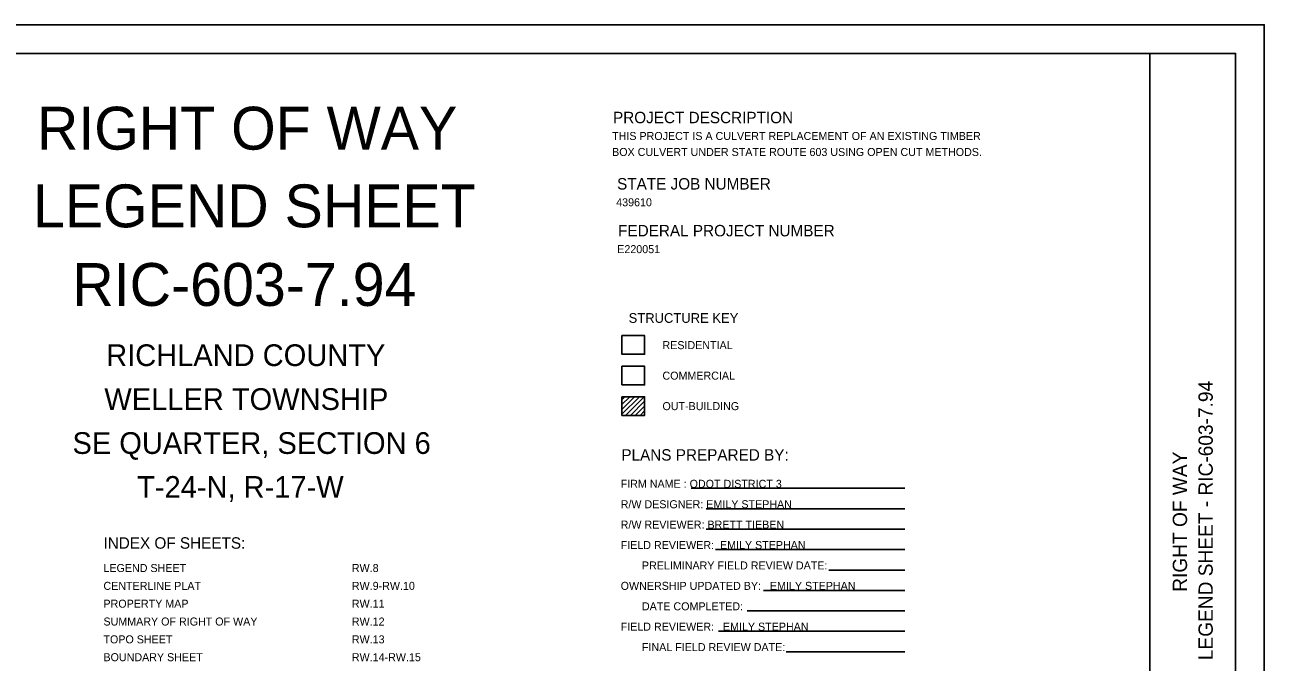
# Model space of a CAD drawing. Extents: x 0 to 34, y 0 to 22.
# Drawn here: x 12.32 to 34, y 10.85 to 22 of the extents above; entities that cross this region are included whole.
import ezdxf

# ---------------------------------------------------------------- set-up
doc = ezdxf.new("R2010")
doc.units = 0
for name, color, linetype in [('SC_Shading1', 7, 'Continuous'), ('SH_Border', 7, 'Continuous'), ('SH_Cut_Line', 7, 'Continuous'), ('SH_Data', 7, 'Continuous'), ('SH_Text', 7, 'Continuous')]:
    doc.layers.add(name, color=color, linetype=linetype)

msp = doc.modelspace()

# ---------------------------------------------------------------- linework, layer by layer
at = {"layer": 'SC_Shading1'}
msp.add_lwpolyline([(22.763, 15.701), (23.16, 15.701), (23.16, 16.027), (22.763, 16.027)], close=True, dxfattribs=at)
at = {"layer": 'SH_Border'}
msp.add_line((32, 0.5), (32, 21.5), dxfattribs=at)
msp.add_lwpolyline([(1.5, 21.5), (33.5, 21.5), (33.5, 0.5), (1.5, 0.5)], close=True, dxfattribs=at)
at = {"layer": 'SH_Cut_Line'}
msp.add_lwpolyline([(0, 0), (34, 0), (34, 22), (0, 22)], close=True, dxfattribs=at)
at = {"layer": 'SH_Text'}
for p, q in [((22.763, 15.491), (22.764, 15.492)), ((22.763, 15.441), (22.814, 15.492)), ((22.763, 15.356), (22.899, 15.492)), ((22.763, 15.271), (22.983, 15.492)), ((22.763, 15.186), (23.068, 15.492)), ((22.827, 15.166), (23.153, 15.492)), ((22.912, 15.166), (23.16, 15.414)), ((22.996, 15.166), (23.16, 15.329)), ((23.081, 15.166), (23.16, 15.245)), ((22.763, 15.171), (22.767, 15.166)), ((23.973, 13.891), (27.71, 13.891)), ((24.237, 13.533), (27.71, 13.533)), ((24.237, 13.176), (27.71, 13.176)), ((24.401, 12.819), (27.71, 12.819)), ((26.382, 12.462), (27.71, 12.462)), ((25.237, 12.105), (27.71, 12.105)), ((24.952, 11.747), (27.71, 11.747)), ((24.455, 11.391), (27.71, 11.391)), ((25.635, 11.033), (27.71, 11.033))]:
    msp.add_line(p, q, dxfattribs=at)
for points in [[(22.763, 16.563), (23.16, 16.563), (23.16, 16.237), (22.763, 16.237)], [(22.763, 15.492), (23.16, 15.492), (23.16, 15.166), (22.763, 15.166)]]:
    msp.add_lwpolyline(points, close=True, dxfattribs=at)

# ---------------------------------------------------------------- texts
at = {"layer": 'SH_Data'}
for s, height, p in [('RIGHT OF WAY', 0.75, (12.527, 19.816)), ('LEGEND SHEET', 0.75, (12.458, 18.457)), (' RIC-603-7.94', 0.75, (12.869, 17.082)), ('    RICHLAND COUNTY    ', 0.38, (13.175, 16.03)), ('    WELLER TOWNSHIP    ', 0.38, (13.143, 15.262)), (' SE QUARTER, SECTION 6 ', 0.38, (13.009, 14.493)), ('     T-24-N, R-17-W    ', 0.38, (13.575, 13.725)), ('INDEX OF SHEETS:', 0.2, (13.692, 12.835)), ('LEGEND SHEET                       ', 0.14, (13.692, 12.427)), ('RW.8  ', 0.14, (18.038, 12.427)), ('CENTERLINE PLAT                    ', 0.14, (13.692, 12.115)), ('RW.9-RW.10          ', 0.14, (18.038, 12.115)), ('PROPERTY MAP                       ', 0.14, (13.692, 11.803)), ('RW.11 ', 0.14, (18.038, 11.803)), ('SUMMARY OF RIGHT OF WAY            ', 0.14, (13.692, 11.491)), ('RW.12 ', 0.14, (18.038, 11.491)), ('TOPO SHEET                         ', 0.14, (13.692, 11.179)), ('RW.13 ', 0.14, (18.038, 11.179)), ('BOUNDARY SHEET                     ', 0.14, (13.692, 10.867)), ('RW.14-RW.15         ', 0.14, (18.038, 10.867))]:
    msp.add_text(s, height=height, dxfattribs=at).set_placement(p)
for s, p in [('LEGEND SHEET - RIC-603-7.94', (33.1, 10.885)), ('RIGHT OF WAY', (32.65, 12.082))]:
    msp.add_text(s, height=0.25, rotation=90, dxfattribs=at).set_placement(p)
at = {"layer": 'SH_Text'}
for s, height, p in [('PROJECT DESCRIPTION', 0.2, (22.607, 20.278)), ('THIS PROJECT IS A CULVERT REPLACEMENT OF AN EXISTING TIMBER           ', 0.14, (22.591, 19.985)), ('BOX CULVERT UNDER STATE ROUTE 603 USING OPEN CUT METHODS.             ', 0.14, (22.591, 19.705)), ('STATE JOB NUMBER', 0.2, (22.678, 19.118)), ('439610                                                                ', 0.14, (22.663, 18.825)), ('FEDERAL PROJECT NUMBER', 0.2, (22.696, 18.299)), ('E220051                                                               ', 0.14, (22.681, 18.005)), ('STRUCTURE KEY', 0.17, (22.88, 16.786)), ('RESIDENTIAL', 0.14, (23.472, 16.326)), ('COMMERCIAL', 0.14, (23.472, 15.792)), ('OUT-BUILDING', 0.14, (23.472, 15.259)), ('PLANS PREPARED BY:', 0.2, (22.753, 14.376)), ('FIRM NAME : ODOT DISTRICT 3', 0.14, (22.741, 13.9)), ('R/W DESIGNER: EMILY STEPHAN', 0.14, (22.741, 13.543)), ('R/W REVIEWER: BRETT TIEBEN', 0.14, (22.741, 13.186)), ('FIELD REVIEWER:  EMILY STEPHAN', 0.14, (22.741, 12.829)), ('PRELIMINARY FIELD REVIEW DATE:', 0.14, (23.113, 12.472)), ('OWNERSHIP UPDATED BY:   EMILY STEPHAN', 0.14, (22.741, 12.115)), ('DATE COMPLETED:', 0.14, (23.113, 11.757)), ('FIELD REVIEWER:   EMILY STEPHAN', 0.14, (22.741, 11.401)), ('FINAL FIELD REVIEW DATE:', 0.14, (23.113, 11.043))]:
    msp.add_text(s, height=height, dxfattribs=at).set_placement(p)

doc.saveas('drawing.dxf')
